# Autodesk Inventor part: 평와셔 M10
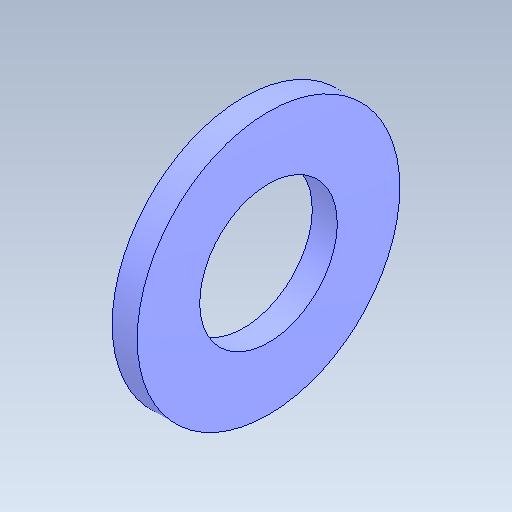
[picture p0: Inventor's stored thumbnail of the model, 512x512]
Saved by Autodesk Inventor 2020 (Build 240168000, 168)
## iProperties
Created: 2024-08
Part Number: 평와셔 M10
Material: 강철, 연강
Description: 평면 와셔
Document SubType Name: Modeling
Designer: oem
Density: 7.85 g/cm^3
Appearance: 기본값
Author: jhkim
Sending System: Autodesk Inventor 2025
Preprocessor: ST-DEVELOPER v20
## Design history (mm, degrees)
node "평와셔 M101"
node "솔리드1"
body "Solid1"
